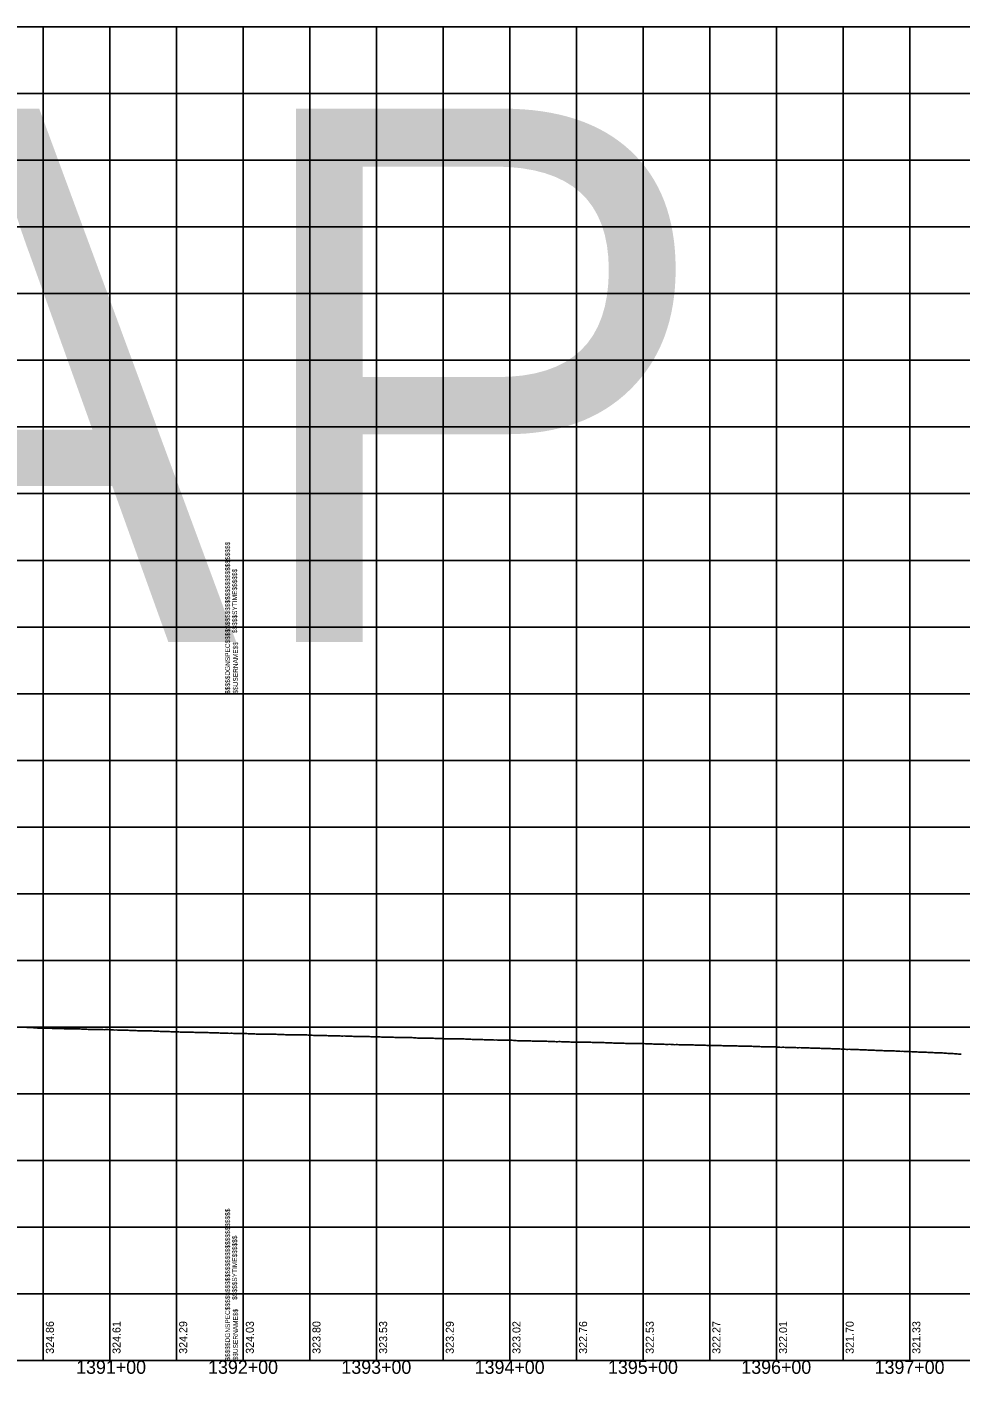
# Model space of a CAD drawing. Extents: x -90830 to 2015517, y -20856 to 836331.
# Drawn here: x 11061 to 11761, y 20053 to 21063 of the extents above; entities that cross this region are included whole.
import ezdxf

# ---------------------------------------------------------------- set-up
doc = ezdxf.new("R2010")
doc.units = 0
for name, color, linetype in [('Level 1', 7, 'Continuous'), ('RD_DDB_Profile_EX', 7, 'Continuous'), ('RD_DDB_StaTX', 7, 'Continuous'), ('RD_DDB_StripGrade', 7, 'Continuous'), ('RD_GPK_Profile_Cell', 7, 'Continuous')]:
    doc.layers.add(name, color=color, linetype=linetype)

msp = doc.modelspace()

# ---------------------------------------------------------------- linework, layer by layer
at = {"layer": 'Level 1'}
for p, q in [((9623.5, 21062.9), (11223.5, 21062.9)), ((11073.5, 21062.9), (11073.5, 20562.9)), ((11123.5, 21062.9), (11123.5, 20562.9)), ((11173.5, 21062.9), (11173.5, 20562.9)), ((11223.5, 21062.9), (11223.5, 20562.9)), ((11223.5, 21062.9), (11223.5, 20562.9)), ((11223.5, 21062.9), (12823.5, 21062.9)), ((11223.5, 21062.9), (11223.5, 20562.9)), ((11273.5, 21062.9), (11273.5, 20562.9)), ((11323.5, 21062.9), (11323.5, 20562.9)), ((11373.5, 21062.9), (11373.5, 20562.9)), ((11423.5, 21062.9), (11423.5, 20562.9)), ((11473.5, 21062.9), (11473.5, 20562.9)), ((11523.5, 21062.9), (11523.5, 20562.9)), ((11573.5, 21062.9), (11573.5, 20562.9)), ((11623.5, 21062.9), (11623.5, 20562.9)), ((11673.5, 21062.9), (11673.5, 20562.9)), ((11723.5, 21062.9), (11723.5, 20562.9)), ((9623.5, 21012.9), (11223.5, 21012.9)), ((11223.5, 21012.9), (12823.5, 21012.9)), ((9623.5, 20962.9), (11223.5, 20962.9)), ((11223.5, 20962.9), (12823.5, 20962.9)), ((9623.5, 20912.9), (11223.5, 20912.9)), ((11223.5, 20912.9), (12823.5, 20912.9)), ((9623.5, 20862.9), (11223.5, 20862.9)), ((11223.5, 20862.9), (12823.5, 20862.9)), ((9623.5, 20812.9), (11223.5, 20812.9)), ((11223.5, 20812.9), (12823.5, 20812.9)), ((9623.5, 20762.9), (11223.5, 20762.9)), ((11223.5, 20762.9), (12823.5, 20762.9)), ((9623.5, 20712.9), (11223.5, 20712.9)), ((11223.5, 20712.9), (12823.5, 20712.9)), ((9623.5, 20662.9), (11223.5, 20662.9)), ((11223.5, 20662.9), (12823.5, 20662.9)), ((9623.5, 20612.9), (11223.5, 20612.9)), ((11223.5, 20612.9), (12823.5, 20612.9)), ((9623.5, 20562.9), (11223.5, 20562.9)), ((9623.5, 20562.9), (11223.5, 20562.9)), ((11073.5, 20562.9), (11073.5, 20062.9)), ((11123.5, 20562.9), (11123.5, 20062.9)), ((11173.5, 20562.9), (11173.5, 20062.9)), ((11223.5, 20562.9), (11223.5, 20062.9)), ((11223.5, 20562.9), (11223.5, 20062.9)), ((11223.5, 20562.9), (12823.5, 20562.9)), ((11223.5, 20562.9), (12823.5, 20562.9)), ((11223.5, 20562.9), (11223.5, 20062.9)), ((11273.5, 20562.9), (11273.5, 20062.9)), ((11323.5, 20562.9), (11323.5, 20062.9)), ((11373.5, 20562.9), (11373.5, 20062.9)), ((11423.5, 20562.9), (11423.5, 20062.9)), ((11473.5, 20562.9), (11473.5, 20062.9)), ((11523.5, 20562.9), (11523.5, 20062.9)), ((11573.5, 20562.9), (11573.5, 20062.9)), ((11623.5, 20562.9), (11623.5, 20062.9)), ((11673.5, 20562.9), (11673.5, 20062.9)), ((11723.5, 20562.9), (11723.5, 20062.9)), ((9623.5, 20512.9), (11223.5, 20512.9)), ((11223.5, 20512.9), (12823.5, 20512.9)), ((9623.5, 20462.9), (11223.5, 20462.9)), ((11223.5, 20462.9), (12823.5, 20462.9)), ((9623.5, 20412.9), (11223.5, 20412.9)), ((11223.5, 20412.9), (12823.5, 20412.9)), ((9623.5, 20362.9), (11223.5, 20362.9)), ((11223.5, 20362.9), (12823.5, 20362.9)), ((9623.5, 20312.9), (11223.5, 20312.9)), ((11223.5, 20312.9), (12823.5, 20312.9)), ((9623.5, 20262.9), (11223.5, 20262.9)), ((11223.5, 20262.9), (12823.5, 20262.9)), ((9623.5, 20212.9), (11223.5, 20212.9)), ((11223.5, 20212.9), (12823.5, 20212.9)), ((9623.5, 20162.9), (11223.5, 20162.9)), ((11223.5, 20162.9), (12823.5, 20162.9)), ((9623.5, 20112.9), (11223.5, 20112.9)), ((11223.5, 20112.9), (12823.5, 20112.9)), ((9623.5, 20062.9), (11223.5, 20062.9)), ((11223.5, 20062.9), (12823.5, 20062.9))]:
    msp.add_line(p, q, dxfattribs=at)
at = {"layer": 'RD_DDB_Profile_EX'}
for points in [[(11061.2, 20312.6), (11062.2, 20312.6), (11063.2, 20312.5), (11064.2, 20312.5), (11065.2, 20312.5), (11066.2, 20312.4), (11067.2, 20312.4), (11068.2, 20312.3), (11069.2, 20312.2), (11070.2, 20312.2), (11071.2, 20312.2), (11072.2, 20312.2), (11073.2, 20312.2), (11074.2, 20312.2), (11075.2, 20312.1), (11076.2, 20312.1), (11077.2, 20312), (11078.2, 20312), (11079.2, 20312), (11080.2, 20311.9), (11081.2, 20311.9), (11082.2, 20311.9), (11083.2, 20311.8), (11084.2, 20311.8), (11085.2, 20311.8), (11086.2, 20311.8), (11087.2, 20311.8), (11088.2, 20311.8), (11089.2, 20311.7), (11090.2, 20311.7), (11091.2, 20311.6), (11092.2, 20311.6), (11093.2, 20311.6), (11094.2, 20311.6), (11095.2, 20311.5), (11096.2, 20311.5), (11097.2, 20311.5), (11098.2, 20311.5), (11099.2, 20311.5), (11100.2, 20311.5), (11101.2, 20311.5), (11102.2, 20311.4), (11103.2, 20311.4), (11104.2, 20311.4), (11105.2, 20311.3), (11106.2, 20311.3), (11107.2, 20311.2), (11108.2, 20311.2), (11109.2, 20311.2), (11110.2, 20311.2), (11111.2, 20311.2), (11112.2, 20311.2), (11113.2, 20311.1), (11114.2, 20311.1), (11115.2, 20311), (11116.2, 20311), (11117.2, 20311), (11118.2, 20311), (11119.2, 20310.9), (11120.2, 20311), (11121.2, 20311), (11122.2, 20311), (11123.2, 20310.9), (11124.2, 20310.9), (11125.2, 20310.9), (11126.2, 20310.8), (11127.2, 20310.7), (11128.2, 20310.8), (11129.2, 20310.7), (11130.2, 20310.6), (11131.2, 20310.6), (11132.2, 20310.6), (11133.2, 20310.6), (11134.2, 20310.6), (11135.2, 20310.6), (11136.2, 20310.6), (11137.2, 20310.5), (11138.2, 20310.4), (11139.2, 20310.4), (11140.2, 20310.4), (11141.2, 20310.3), (11142.2, 20310.3), (11143.2, 20310.3), (11144.2, 20310.2)], [(11144.2, 20310.2), (11145.2, 20310.2), (11146.2, 20310.2), (11147.2, 20310.2), (11148.2, 20310.2), (11149.2, 20310.2), (11150.2, 20310.1), (11151.2, 20310.1), (11152.2, 20310.1), (11153.2, 20310), (11154.2, 20310), (11155.2, 20310), (11156.2, 20309.9), (11157.2, 20309.8), (11158.2, 20309.8), (11159.2, 20309.8), (11160.2, 20309.8), (11161.2, 20309.7), (11162.2, 20309.6), (11163.2, 20309.7), (11164.2, 20309.6), (11165.2, 20309.6), (11166.2, 20309.5), (11167.2, 20309.6), (11168.2, 20309.5), (11169.2, 20309.4), (11170.2, 20309.4), (11171.2, 20309.4), (11172.2, 20309.4), (11173.2, 20309.3), (11174.2, 20309.3), (11175.2, 20309.3), (11176.2, 20309.2), (11177.2, 20309.2), (11178.2, 20309.2), (11179.2, 20309.1), (11180.2, 20309.1), (11181.2, 20309.1), (11182.2, 20309.1), (11183.2, 20309.1), (11184.2, 20309.1), (11185.2, 20309.1), (11186.2, 20309), (11187.2, 20308.9), (11188.2, 20308.9), (11189.2, 20308.9), (11190.2, 20308.8), (11191.2, 20308.8), (11192.2, 20308.8), (11193.2, 20308.8), (11194.2, 20308.8), (11195.2, 20308.8), (11196.2, 20308.8), (11197.2, 20308.8), (11198.2, 20308.7), (11199.2, 20308.7), (11200.2, 20308.6), (11201.2, 20308.6), (11202.2, 20308.6), (11203.2, 20308.5), (11204.2, 20308.5), (11205.2, 20308.5), (11206.2, 20308.4), (11207.2, 20308.4), (11208.2, 20308.4), (11209.2, 20308.3), (11210.2, 20308.3), (11211.2, 20308.3), (11212.2, 20308.3), (11213.2, 20308.2), (11214.2, 20308.3), (11215.2, 20308.3), (11216.2, 20308.2), (11217.2, 20308.2), (11218.2, 20308.1), (11219.2, 20308.1), (11220.2, 20308.1), (11221.2, 20308.1), (11222.2, 20308.1), (11223.2, 20308.1), (11224.2, 20308), (11225.2, 20308), (11226.2, 20308), (11227.2, 20307.9), (11228.2, 20307.8), (11229.2, 20307.8), (11230.2, 20307.8), (11231.2, 20307.8), (11232.2, 20307.8), (11233.2, 20307.7), (11234.2, 20307.7), (11235.2, 20307.7), (11236.2, 20307.7), (11237.2, 20307.7), (11238.2, 20307.6), (11239.2, 20307.6), (11240.2, 20307.5), (11241.2, 20307.5), (11242.2, 20307.6), (11243.2, 20307.6), (11244.2, 20307.5)], [(11244.2, 20307.5), (11245.2, 20307.5), (11246.2, 20307.5), (11247.2, 20307.5), (11248.2, 20307.5), (11249.2, 20307.4), (11250.2, 20307.4), (11251.2, 20307.4), (11252.2, 20307.4), (11253.2, 20307.4), (11254.2, 20307.3), (11255.2, 20307.2), (11256.2, 20307.2), (11257.2, 20307.2), (11258.2, 20307.2), (11259.2, 20307.2), (11260.2, 20307.2), (11261.2, 20307.2), (11262.2, 20307.2), (11263.2, 20307.2), (11264.2, 20307.1), (11265.2, 20307.1), (11266.2, 20307.1), (11267.2, 20307), (11268.2, 20307), (11269.2, 20307), (11270.2, 20307), (11271.2, 20307), (11272.2, 20306.9), (11273.2, 20306.9), (11274.2, 20306.9), (11275.2, 20306.8), (11276.2, 20306.7), (11277.2, 20306.7), (11278.2, 20306.7), (11279.2, 20306.6), (11280.2, 20306.6), (11281.2, 20306.6), (11282.2, 20306.5), (11283.2, 20306.5), (11284.2, 20306.5), (11285.2, 20306.5), (11286.2, 20306.5), (11287.2, 20306.4), (11288.2, 20306.4), (11289.2, 20306.4), (11290.2, 20306.4), (11291.2, 20306.4), (11292.2, 20306.4), (11293.2, 20306.4), (11294.2, 20306.4), (11295.2, 20306.3), (11296.2, 20306.3), (11297.2, 20306.2), (11298.2, 20306.2), (11299.2, 20306.3), (11300.2, 20306.2), (11301.2, 20306.2), (11302.2, 20306.1), (11303.2, 20306), (11304.2, 20306), (11305.2, 20306), (11306.2, 20305.9), (11307.2, 20305.9), (11308.2, 20305.9), (11309.2, 20305.9), (11310.2, 20305.9), (11311.2, 20305.9), (11312.2, 20305.8), (11313.2, 20305.8), (11314.2, 20305.8), (11315.2, 20305.8), (11316.2, 20305.8), (11317.2, 20305.8), (11318.2, 20305.8), (11319.2, 20305.7), (11320.2, 20305.7), (11321.2, 20305.6), (11322.2, 20305.6), (11323.2, 20305.5), (11324.2, 20305.6), (11325.2, 20305.5), (11326.2, 20305.5), (11327.2, 20305.4), (11328.2, 20305.4), (11329.2, 20305.4), (11330.2, 20305.4), (11331.2, 20305.3), (11332.2, 20305.4), (11333.2, 20305.4), (11334.2, 20305.4), (11335.2, 20305.3), (11336.2, 20305.3), (11337.2, 20305.2), (11338.2, 20305.2), (11339.2, 20305.2), (11340.2, 20305.2), (11341.2, 20305.1), (11342.2, 20305.1), (11343.2, 20305.1), (11344.2, 20305.1)], [(11344.2, 20305.1), (11345.2, 20305.1), (11346.2, 20305.1), (11347.2, 20305.1), (11348.2, 20305.1), (11349.2, 20305.1), (11350.2, 20305), (11351.2, 20304.9), (11352.2, 20304.9), (11353.2, 20304.8), (11354.2, 20304.7), (11355.2, 20304.7), (11356.2, 20304.7), (11357.2, 20304.7), (11358.2, 20304.7), (11359.2, 20304.6), (11360.2, 20304.6), (11361.2, 20304.6), (11362.2, 20304.6), (11363.2, 20304.7), (11364.2, 20304.6), (11365.2, 20304.6), (11366.2, 20304.6), (11367.2, 20304.4), (11368.2, 20304.4), (11369.2, 20304.4), (11370.2, 20304.4), (11371.2, 20304.4), (11372.2, 20304.4), (11373.2, 20304.3), (11374.2, 20304.2), (11375.2, 20304.2), (11376.2, 20304.2), (11377.2, 20304.2), (11378.2, 20304.2), (11379.2, 20304.1), (11380.2, 20304.1), (11381.2, 20304.1), (11382.2, 20304), (11383.2, 20304.1), (11384.2, 20304.1), (11385.2, 20304), (11386.2, 20304), (11387.2, 20304.1), (11388.2, 20304), (11389.2, 20304), (11390.2, 20303.9), (11391.2, 20303.9), (11392.2, 20303.8), (11393.2, 20303.8), (11394.2, 20303.8), (11395.2, 20303.7), (11396.2, 20303.6), (11397.2, 20303.6), (11398.2, 20303.7), (11399.2, 20303.6), (11400.2, 20303.5), (11401.2, 20303.5), (11402.2, 20303.5), (11403.2, 20303.5), (11404.2, 20303.4), (11405.2, 20303.4), (11406.2, 20303.4), (11407.2, 20303.4), (11408.2, 20303.4), (11409.2, 20303.3), (11410.2, 20303.3), (11411.2, 20303.3), (11412.2, 20303.2), (11413.2, 20303.3), (11414.2, 20303.2), (11415.2, 20303.1), (11416.2, 20303.1), (11417.2, 20303.1), (11418.2, 20303.1), (11419.2, 20303.2), (11420.2, 20303.1), (11421.2, 20303), (11422.2, 20303), (11423.2, 20303), (11424.2, 20303), (11425.2, 20303), (11426.2, 20302.9), (11427.2, 20302.8), (11428.2, 20302.8), (11429.2, 20302.7), (11430.2, 20302.7), (11431.2, 20302.7), (11432.2, 20302.7), (11433.2, 20302.6), (11434.2, 20302.6), (11435.2, 20302.6), (11436.2, 20302.6), (11437.2, 20302.5), (11438.2, 20302.5), (11439.2, 20302.5), (11440.2, 20302.4), (11441.2, 20302.4), (11442.2, 20302.3), (11443.2, 20302.3), (11444.2, 20302.4)], [(11444.2, 20302.4), (11445.2, 20302.3), (11446.2, 20302.3), (11447.2, 20302.3), (11448.2, 20302.3), (11449.2, 20302.3), (11450.2, 20302.3), (11451.2, 20302.3), (11452.2, 20302.2), (11453.2, 20302.2), (11454.2, 20302.1), (11455.2, 20302), (11456.2, 20302), (11457.2, 20302), (11458.2, 20301.9), (11459.2, 20301.9), (11460.2, 20302), (11461.2, 20302), (11462.2, 20301.9), (11463.2, 20301.9), (11464.2, 20301.9), (11465.2, 20301.8), (11466.2, 20301.8), (11467.2, 20301.8), (11468.2, 20301.8), (11469.2, 20301.7), (11470.2, 20301.7), (11471.2, 20301.7), (11472.2, 20301.7), (11473.2, 20301.7), (11474.2, 20301.7), (11475.2, 20301.7), (11476.2, 20301.6), (11477.2, 20301.6), (11478.2, 20301.6), (11479.2, 20301.6), (11480.2, 20301.6), (11481.2, 20301.5), (11482.2, 20301.5), (11483.2, 20301.5), (11484.2, 20301.5), (11485.2, 20301.4), (11486.2, 20301.4), (11487.2, 20301.3), (11488.2, 20301.3), (11489.2, 20301.3), (11490.2, 20301.3), (11491.2, 20301.3), (11492.2, 20301.3), (11493.2, 20301.3), (11494.2, 20301.3), (11495.2, 20301.2), (11496.2, 20301.1), (11497.2, 20301.2), (11498.2, 20301.1), (11499.2, 20301), (11500.2, 20301), (11501.2, 20300.9), (11502.2, 20300.9), (11503.2, 20300.9), (11504.2, 20300.9), (11505.2, 20300.9), (11506.2, 20300.9), (11507.2, 20300.8), (11508.2, 20300.8), (11509.2, 20300.8), (11510.2, 20300.7), (11511.2, 20300.6), (11512.2, 20300.6), (11513.2, 20300.7), (11514.2, 20300.7), (11515.2, 20300.6), (11516.2, 20300.6), (11517.2, 20300.6), (11518.2, 20300.5), (11519.2, 20300.6), (11520.2, 20300.5), (11521.2, 20300.5), (11522.2, 20300.5), (11523.2, 20300.5), (11524.2, 20300.5), (11525.2, 20300.4), (11526.2, 20300.4), (11527.2, 20300.3), (11528.2, 20300.3), (11529.2, 20300.3), (11530.2, 20300.3), (11531.2, 20300.2), (11532.2, 20300.2), (11533.2, 20300.2), (11534.2, 20300.2), (11535.2, 20300.1), (11536.2, 20300.1), (11537.2, 20300), (11538.2, 20300), (11539.2, 20300), (11540.2, 20299.9), (11541.2, 20299.9), (11542.2, 20299.9), (11543.2, 20300), (11544.2, 20299.9)], [(11544.2, 20299.9), (11545.2, 20299.8), (11546.2, 20299.8), (11547.2, 20299.7), (11548.2, 20299.8), (11549.2, 20299.8), (11550.2, 20299.7), (11551.2, 20299.7), (11552.2, 20299.6), (11553.2, 20299.6), (11554.2, 20299.5), (11555.2, 20299.5), (11556.2, 20299.5), (11557.2, 20299.5), (11558.2, 20299.5), (11559.2, 20299.5), (11560.2, 20299.5), (11561.2, 20299.5), (11562.2, 20299.4), (11563.2, 20299.4), (11564.2, 20299.4), (11565.2, 20299.4), (11566.2, 20299.3), (11567.2, 20299.3), (11568.2, 20299.3), (11569.2, 20299.3), (11570.2, 20299.3), (11571.2, 20299.2), (11572.2, 20299.2), (11573.2, 20299.2), (11574.2, 20299.2), (11575.2, 20299.1), (11576.2, 20299.1), (11577.2, 20299.1), (11578.2, 20299.1), (11579.2, 20299.1), (11580.2, 20299), (11581.2, 20299), (11582.2, 20299), (11583.2, 20298.9), (11584.2, 20298.9), (11585.2, 20298.9), (11586.2, 20298.9), (11587.2, 20298.8), (11588.2, 20298.9), (11589.2, 20298.9), (11590.2, 20298.9), (11591.2, 20298.9), (11592.2, 20298.9), (11593.2, 20298.8), (11594.2, 20298.8), (11595.2, 20298.7), (11596.2, 20298.7), (11597.2, 20298.7), (11598.2, 20298.6), (11599.2, 20298.6), (11600.2, 20298.5), (11601.2, 20298.5), (11602.2, 20298.5), (11603.2, 20298.5), (11604.2, 20298.6), (11605.2, 20298.5), (11606.2, 20298.4), (11607.2, 20298.4), (11608.2, 20298.4), (11609.2, 20298.3), (11610.2, 20298.3), (11611.2, 20298.3), (11612.2, 20298.2), (11613.2, 20298.2), (11614.2, 20298.2), (11615.2, 20298.1), (11616.2, 20298.2), (11617.2, 20298.2), (11618.2, 20298.1), (11619.2, 20298.1), (11620.2, 20298.1), (11621.2, 20298.1), (11622.2, 20298), (11623.2, 20298), (11624.2, 20297.9), (11625.2, 20297.9), (11626.2, 20297.8), (11627.2, 20297.7), (11628.2, 20297.8), (11629.2, 20297.8), (11630.2, 20297.7), (11631.2, 20297.7), (11632.2, 20297.7), (11633.2, 20297.7), (11634.2, 20297.6), (11635.2, 20297.6), (11636.2, 20297.5), (11637.2, 20297.5), (11638.2, 20297.5), (11639.2, 20297.4), (11640.2, 20297.4), (11641.2, 20297.5), (11642.2, 20297.4), (11643.2, 20297.4), (11644.2, 20297.4)], [(11644.2, 20297.4), (11645.2, 20297.4), (11646.2, 20297.4), (11647.2, 20297.3), (11648.2, 20297.3), (11649.2, 20297.1), (11650.2, 20297.1), (11651.2, 20297.2), (11652.2, 20297.1), (11653.2, 20297.1), (11654.2, 20297.1), (11655.2, 20297), (11656.2, 20297), (11657.2, 20296.9), (11658.2, 20296.9), (11659.2, 20296.9), (11660.2, 20296.9), (11661.2, 20296.9), (11662.2, 20296.9), (11663.2, 20296.8), (11664.2, 20296.8), (11665.2, 20296.7), (11666.2, 20296.7), (11667.2, 20296.7), (11668.2, 20296.7), (11669.2, 20296.6), (11670.2, 20296.5), (11671.2, 20296.5), (11672.2, 20296.4), (11673.2, 20296.4), (11674.2, 20296.4), (11675.2, 20296.3), (11676.2, 20296.2), (11677.2, 20296.2), (11678.2, 20296.3), (11679.2, 20296.2), (11680.2, 20296.1), (11681.2, 20296.1), (11682.2, 20296), (11683.2, 20296), (11684.2, 20296), (11685.2, 20296), (11686.2, 20295.9), (11687.2, 20295.9), (11688.2, 20295.9), (11689.2, 20295.8), (11690.2, 20295.8), (11691.2, 20295.8), (11692.2, 20295.7), (11693.2, 20295.7), (11694.2, 20295.6), (11695.2, 20295.6), (11696.2, 20295.5), (11697.2, 20295.5), (11698.2, 20295.4), (11699.2, 20295.4), (11700.2, 20295.4), (11701.2, 20295.4), (11702.2, 20295.3), (11703.2, 20295.3), (11704.2, 20295.2), (11705.2, 20295.2), (11706.2, 20295.2), (11707.2, 20295.2), (11708.2, 20295.1), (11709.2, 20295), (11710.2, 20295.1), (11711.2, 20295.1), (11712.2, 20295), (11713.2, 20294.9), (11714.2, 20294.9), (11715.2, 20294.8), (11716.2, 20294.8), (11717.2, 20294.7), (11718.2, 20294.8), (11719.2, 20294.7), (11720.2, 20294.7), (11721.2, 20294.7), (11722.2, 20294.6), (11723.2, 20294.5), (11724.2, 20294.5), (11725.2, 20294.4), (11726.2, 20294.4), (11727.2, 20294.4), (11728.2, 20294.4), (11729.2, 20294.3), (11730.2, 20294.2), (11731.2, 20294.2), (11732.2, 20294.2), (11733.2, 20294.2), (11734.2, 20294.2), (11735.2, 20294.1), (11736.2, 20294), (11737.2, 20293.9), (11738.2, 20293.9), (11739.2, 20293.9), (11740.2, 20293.8), (11741.2, 20293.8), (11742.2, 20293.7), (11743.2, 20293.6), (11744.2, 20293.6)], [(11744.2, 20293.6), (11745.2, 20293.5), (11746.2, 20293.5), (11747.2, 20293.5), (11748.2, 20293.5), (11749.2, 20293.4), (11750.2, 20293.3), (11751.2, 20293.3), (11752.2, 20293.2), (11753.2, 20293.2), (11754.2, 20293.1), (11755.2, 20293.1), (11756.2, 20293), (11757.2, 20292.9), (11758.2, 20292.9), (11759.2, 20292.8), (11760.2, 20292.7), (11761.2, 20292.7), (11762.2, 20292.5)]]:
    msp.add_lwpolyline(points, dxfattribs=at)
at = {"layer": 'RD_GPK_Profile_Cell'}
msp.add_line((9644.2, 20062.9), (12444.2, 20062.9), dxfattribs=at)

# ---------------------------------------------------------------- texts
at = {"layer": 'Level 1'}
for s, p in [('$$$$$DGNSPEC$$$$$$$$$$$$$$$$$$$$$$$$$$$$', (11213.6, 20562.8)), ('$$$$$SYTIME$$$$$$', (11218.9, 20608.4)), ('$$USERNAME$$', (11219.5, 20563)), ('$$$$$DGNSPEC$$$$$$$$$$$$$$$$$$$$$$$$$$$$', (11213.6, 20062.8)), ('$$$$$SYTIME$$$$$$', (11218.9, 20108.4)), ('$$USERNAME$$', (11219.5, 20063))]:
    msp.add_text(s, height=3.544, rotation=90, dxfattribs=at).set_placement(p)
at = {"layer": 'RD_DDB_StaTX'}
for s, p in [('1391+00', (11098.2, 20052.9)), ('1392+00', (11197.2, 20052.9)), ('1393+00', (11297.2, 20052.9)), ('1394+00', (11397.2, 20052.9)), ('1395+00', (11497.2, 20052.9)), ('1396+00', (11597.2, 20052.9)), ('1397+00', (11697.2, 20052.9))]:
    msp.add_text(s, height=10, dxfattribs=at).set_placement(p)
at = {"layer": 'RD_DDB_StripGrade'}
for s, p in [('324.86', (11081.5, 20067.9)), ('324.61', (11131.5, 20067.9)), ('324.29', (11181.5, 20067.9)), ('324.03', (11231.5, 20067.9)), ('323.80', (11281.5, 20067.9)), ('323.53', (11331.5, 20067.9)), ('323.29', (11381.5, 20067.9)), ('323.02', (11431.5, 20067.9)), ('322.76', (11481.5, 20067.9)), ('322.53', (11531.5, 20067.9)), ('322.27', (11581.5, 20067.9)), ('322.01', (11631.5, 20067.9)), ('321.70', (11681.5, 20067.9)), ('321.33', (11731.5, 20067.9))]:
    msp.add_text(s, height=6, rotation=90, dxfattribs=at).set_placement(p)
at = {"layer": 'RD_GPK_Profile_Cell'}
msp.add_text('NOGAP', height=400, dxfattribs=at).set_placement((9644.2, 20601.6))

doc.saveas('drawing.dxf')
